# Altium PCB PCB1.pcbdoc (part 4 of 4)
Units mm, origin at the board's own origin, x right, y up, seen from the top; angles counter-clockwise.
Board outline 77.9 x 107.7 mm, 4 copper layers (Top Layer, Inner1, Inner2, Bottom Layer); 106 components, 123 nets, 650 pads, 272 vias.
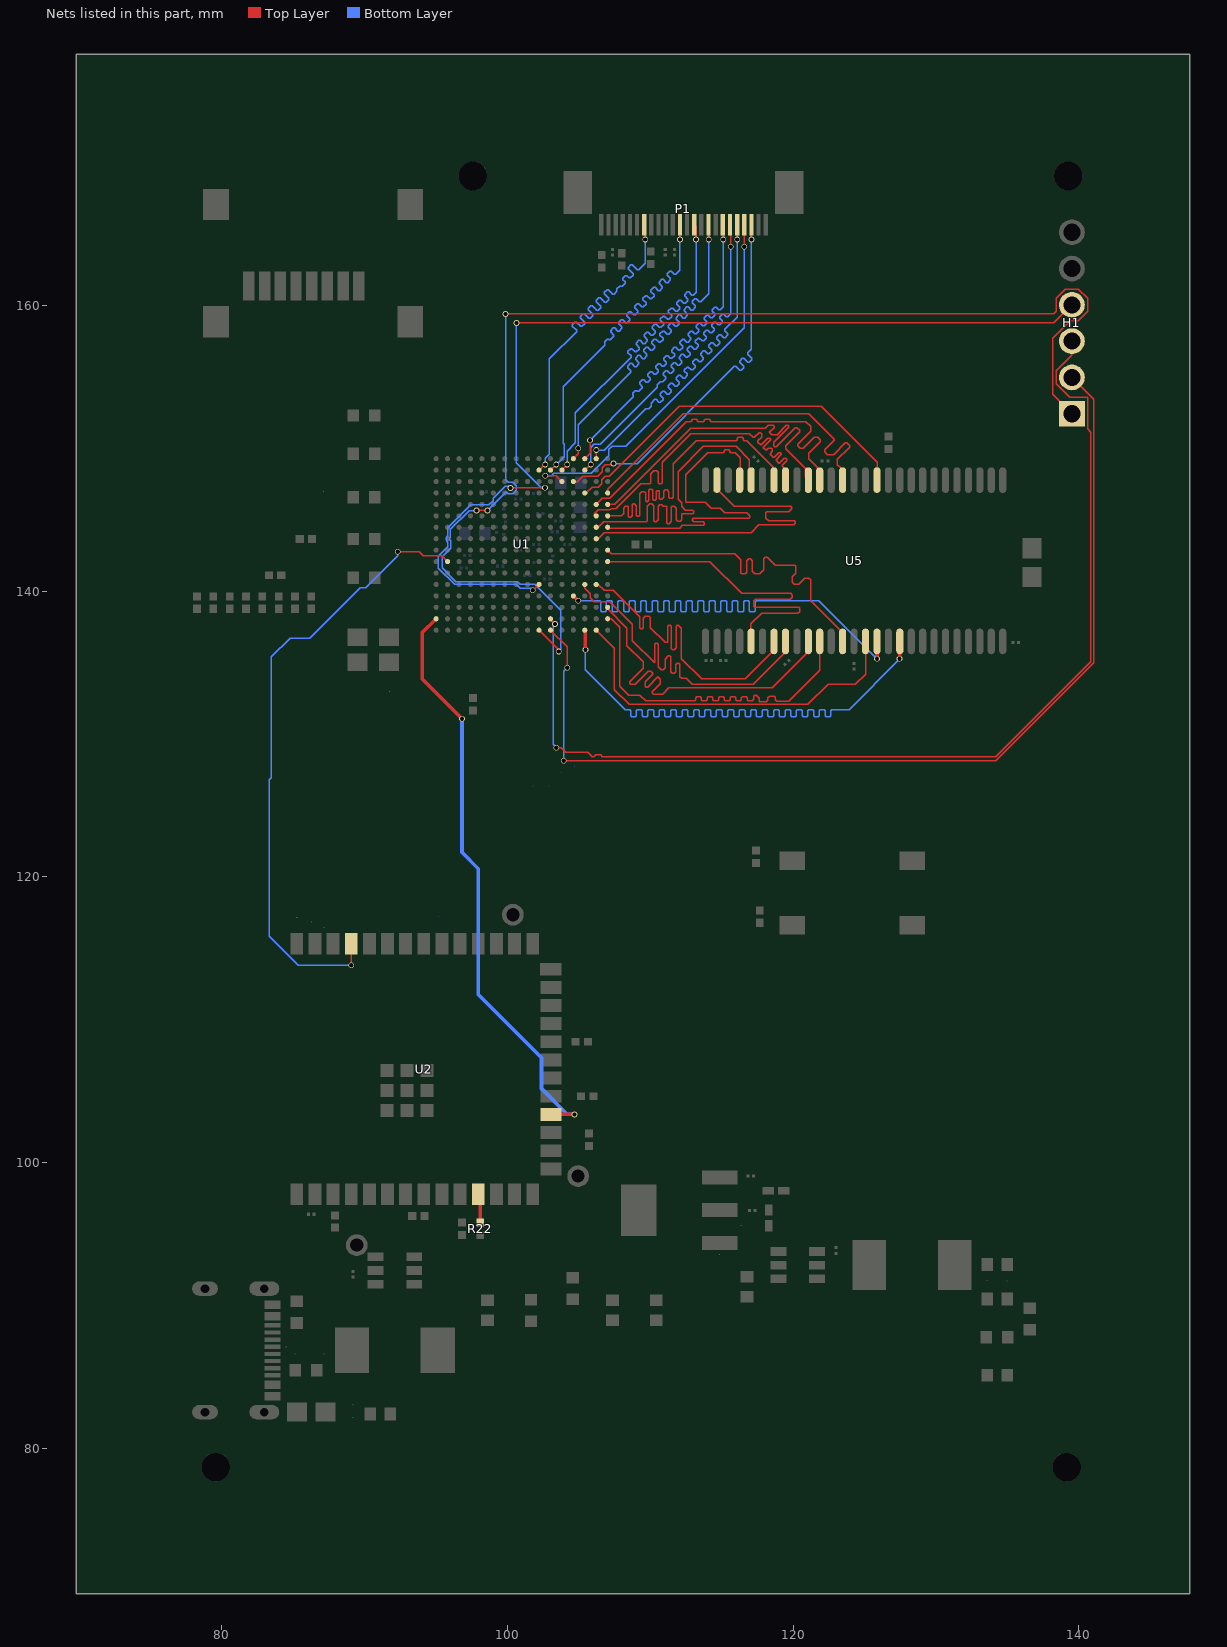
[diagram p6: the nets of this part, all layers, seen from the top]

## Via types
v1: diameter 0.4, hole 0.3, Top Layer to Bottom Layer, 269 vias
v2: diameter 0.5, hole 0.3, Top Layer to Bottom Layer, 3 vias

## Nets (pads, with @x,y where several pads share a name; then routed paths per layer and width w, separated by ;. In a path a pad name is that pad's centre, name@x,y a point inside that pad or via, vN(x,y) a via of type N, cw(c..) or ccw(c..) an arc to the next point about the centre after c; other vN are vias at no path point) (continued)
SD_DQ2: U1.K16 U5.5 | length 25.6
  Top Layer w0.1: U1.K16@107.024,142.06 114.162,142.06 116.391,139.831 119.82,139.831 119.947,139.704 119.947,139.577 119.803,139.434 117.372,139.434 117.262,139.323 117.262,138.919 117.322,138.859 120.384,138.859 120.455,138.788 120.455,138.561 120.329,138.435 117.789,138.435 117.048,137.694 117.048,136.873 117.065,136.856 U5.5@117.065,136.602
SD_DQ3: U1.M15 U5.7 | length 24.8
  Top Layer w0.1: U1.M15@106.224,140.46 106.303,140.46 106.318,140.445 106.366,140.445 106.769,140.042 107.417,140.042 109.263,138.195 109.263,137.418 109.334,137.347 109.434,137.347 109.505,137.418 109.505,138.095 109.66,138.25 109.914,138.25 110.014,138.15 110.014,137.445 111.057,136.402 111.184,136.402 111.242,136.46 111.242,137.545 111.312,137.616 111.412,137.616 111.483,137.545 111.483,135.976 111.565,135.894 111.692,135.894 111.815,136.018 111.815,137.545 111.874,137.604 111.958,137.604 112.18,137.382 112.18,135.279 113.597,133.862 116.65,133.862 118.521,135.733 118.521,136.331 118.538,136.348 118.538,136.475 U5.7@118.665,136.602
SD_DQ4: U1.M14 U5.8 | length 25.8
  Top Layer w0.1: U1.M14@105.424,140.46 105.424,140.2 105.806,139.818 105.806,139.538 106.102,139.242 107.182,139.242 108.744,137.68 108.744,136.529 110.302,134.971 110.334,135.003 110.334,136.275 110.404,136.346 110.504,136.346 110.575,136.275 110.575,134.698 110.776,134.497 110.93,134.497 111.049,134.616 111.049,135.238 111.267,135.457 111.367,135.457 111.438,135.386 111.438,134.343 111.538,134.243 111.692,134.243 111.784,134.335 111.784,134.831 111.902,134.949 112.002,134.949 112.073,134.878 112.073,134.011 112.2,133.884 112.54,133.884 112.943,133.481 117.214,133.481 119.622,135.889 119.622,136.445 U5.8@119.465,136.602
SD_DQ5: U1.P16 U5.10 | length 25.6
  Top Layer w0.1: U1.P16@107.024,138.86 107.024,138.751 108.369,137.406 108.369,136.169 109.503,135.035 109.503,134.581 108.573,133.652 108.573,133.552 108.644,133.481 108.964,133.481 109.853,134.37 110.041,134.37 110.168,134.243 110.168,134.177 109.647,133.657 109.647,133.341 109.718,133.271 109.818,133.271 110.543,133.995 110.711,133.826 110.711,133.504 110.161,132.953 110.161,132.853 110.231,132.782 110.866,132.782 111.311,133.227 118.542,133.227 121.065,135.75 U5.10@121.065,136.602
SD_DQ6: U1.R16 U5.11 | length 25.2
  Top Layer w0.1: U1.R16@107.024,138.06 107.288,138.06 107.882,137.466 107.882,133.354 108.513,132.723 109.275,132.723 109.676,132.322 113.117,132.322 113.188,132.393 113.188,132.521 113.259,132.592 113.517,132.592 113.588,132.521 113.588,132.393 113.659,132.322 113.917,132.322 113.988,132.393 113.988,132.521 114.059,132.592 114.317,132.592 114.388,132.521 114.388,132.393 114.459,132.322 114.717,132.322 114.788,132.393 114.788,132.521 114.859,132.592 115.117,132.592 115.188,132.521 115.188,132.393 115.259,132.322 115.517,132.322 115.588,132.393 115.588,132.521 115.659,132.592 115.917,132.592 115.988,132.521 115.988,132.393 116.059,132.322 116.317,132.322 116.388,132.393 116.388,132.521 116.459,132.592 116.717,132.592 116.788,132.521 116.788,132.393 116.859,132.322 117.136,132.322 117.236,132.422 117.236,132.648 117.307,132.719 117.407,132.719 117.613,132.513 117.613,132.262 118.125,132.262 118.225,132.362 118.225,132.521 118.352,132.648 118.677,132.648 118.748,132.578 118.748,132.392 118.848,132.292 119.679,132.292 121.852,134.465 U5.11@121.852,136.097
SD_DQ7: U1.J16 U5.13 | length 25.2
  Top Layer w0.1: U1.J16@107.024,142.86 107.259,142.625 115.91,142.625 116.347,142.188 116.347,141.286 116.418,141.215 116.659,141.215 116.759,141.315 116.759,142.117 116.896,142.253 117.016,142.253 117.155,142.115 117.155,141.38 117.319,141.215 117.648,141.215 117.931,141.498 117.931,142.26 118.042,142.371 118.185,142.371 118.753,141.803 118.757,141.807 120.13,141.807 120.201,141.736 120.201,141.237 119.947,140.983 119.947,140.609 120.09,140.466 120.387,140.466 120.822,140.902 121.09,140.902 121.219,140.772 121.219,139.338 ; 121.219,139.337 123.465,137.091 U5.13@123.465,136.602
SD_DQ8: U1.D16 U5.42 | length 25.2
  Top Layer w0.1: U1.D16@107.024,146.86 107.024,147.114 112.314,152.404 121.09,152.404 122.868,150.626 122.868,150.545 122.212,149.889 122.212,149.737 122.4,149.549 122.834,149.549 123.657,150.372 123.757,150.372 123.955,150.174 123.955,150.062 123.884,149.991 123.878,149.991 123.101,149.214 123.101,148.848 123.338,148.611 123.338,148.013 U5.42@123.465,147.886
SD_DQ9: U1.E15 U5.44 | length 25
  Top Layer w0.1: U1.E15@106.224,146.06 106.642,146.478 107.182,146.478 112.537,151.833 112.837,151.833 112.907,151.903 112.907,151.952 112.978,152.023 113.237,152.023 113.307,151.952 113.307,151.903 113.378,151.833 113.723,151.833 113.794,151.903 113.794,151.952 113.865,152.023 114.123,152.023 114.194,151.952 114.194,151.903 114.265,151.833 120.899,151.833 121.217,151.515 121.217,151.176 120.328,150.287 120.328,150.179 120.515,149.991 120.709,149.991 121.471,150.753 121.725,150.753 121.894,150.584 121.894,150.442 121.09,149.638 121.09,149.259 121.674,148.675 121.674,148.077 U5.44@121.865,147.886
SD_DQ10: U1.E16 U5.45 | length 25
  Top Layer w0.1: U1.E16@107.024,146.06 107.507,146.06 112.835,151.388 118.052,151.388 118.25,151.586 118.606,151.586 118.677,151.515 118.677,151.429 118.344,151.096 118.502,150.938 118.874,150.938 119.522,151.586 119.622,151.586 119.693,151.515 119.693,151.448 118.647,150.402 118.647,150.175 118.717,150.105 118.817,150.105 120.151,151.438 120.251,151.438 120.455,151.234 120.455,151.134 119.494,150.173 119.494,149.946 120.717,148.723 120.717,148.718 120.851,148.584 120.851,147.986 120.951,147.886 U5.45@121.065,147.886
SD_DQ11: U1.F15 U5.47 | length 25.1
  Top Layer w0.1: U1.F15@106.224,145.26 106.097,145.387 106.097,145.412 106.363,145.678 107.182,145.678 107.273,145.769 107.597,145.769 109.335,147.507 109.97,147.507 110.041,147.578 110.041,148.213 110.244,148.416 110.449,148.416 110.549,148.316 110.549,147.578 110.62,147.507 110.769,147.507 110.84,147.578 110.84,149.012 112.835,151.007 116.942,151.007 117.202,150.747 117.286,150.747 117.617,151.078 117.717,151.078 117.788,151.007 117.788,150.753 117.534,150.499 117.534,150.415 117.719,150.23 117.772,150.23 118.24,150.697 118.352,150.697 118.423,150.626 118.423,150.581 117.915,150.073 117.915,150.034 118.114,149.835 118.271,149.991 118.487,149.991 118.55,149.928 118.55,149.768 118.392,149.61 118.392,149.557 118.593,149.356 118.677,149.356 119.002,149.681 119.114,149.681 119.185,149.61 119.185,149.561 118.804,149.18 118.804,149.145 118.999,148.95 119.046,148.95 119.395,149.3 119.495,149.3 119.566,149.229 119.566,149.131 119.228,148.793 119.228,148.721 119.465,148.484 U5.47@119.465,147.886
SD_DQ12: U1.F16 U5.48 | length 25.1
  Top Layer w0.1: U1.F16@107.024,145.26 107.977,145.26 108.136,145.419 108.136,145.8 108.263,145.927 108.429,145.927 108.473,145.883 108.473,145.236 108.544,145.165 108.644,145.165 108.752,145.273 108.752,146.035 108.81,146.093 108.898,146.093 109.033,145.958 109.033,145.296 109.108,145.221 109.208,145.221 109.279,145.292 109.279,146.816 109.406,146.943 109.592,146.943 109.672,146.863 109.672,146.308 109.743,146.237 109.811,146.237 109.914,146.34 109.914,147.065 109.976,147.128 110.11,147.128 110.18,147.057 110.18,146.435 110.251,146.364 110.351,146.364 110.422,146.435 110.422,146.943 110.486,147.007 110.612,147.007 110.647,146.972 110.647,146.491 110.718,146.42 110.818,146.42 110.959,146.562 110.959,146.972 111.057,147.07 111.184,147.07 111.311,146.943 111.311,146.562 111.382,146.491 111.55,146.491 111.621,146.562 111.621,148.904 113.216,150.499 116.024,150.499 116.095,150.57 116.095,150.682 116.166,150.753 116.424,150.753 116.495,150.682 116.495,150.57 116.566,150.499 116.772,150.499 118.606,148.664 118.606,147.986 118.665,147.928 U5.48@118.665,147.886
SD_DQ13: U1.G15 U5.50 | length 25.1
  Top Layer w0.1: U1.G15@106.224,144.46 106.365,144.46 106.747,144.842 109.718,144.842 109.787,144.911 109.787,145.927 109.97,146.11 110.112,146.11 110.239,145.983 110.239,144.911 110.309,144.84 110.409,144.84 110.549,144.98 110.549,145.927 110.676,146.054 110.803,146.054 110.93,145.927 111.146,145.927 111.146,144.784 111.217,144.713 111.317,144.713 111.476,144.873 111.476,145.87 111.533,145.927 111.692,145.927 111.819,145.8 111.819,144.984 111.919,144.884 112.1,144.884 112.2,144.984 112.2,145.377 112.241,145.419 112.962,145.419 113.033,145.49 113.033,145.59 112.954,145.668 112.459,145.668 112.2,145.927 112.2,146.168 111.957,146.411 111.957,148.358 113.718,150.118 116.01,150.118 116.946,149.181 116.946,148.005 U5.50@117.065,147.886
SD_DQ14: U1.G16 U5.51 | length 25
  Top Layer w0.1: U1.G16@107.024,144.46 107.087,144.396 112.066,144.396 112.26,144.59 113.724,144.59 113.795,144.661 113.795,144.761 113.724,144.831 113.041,144.831 112.929,144.944 112.929,145.005 113.023,145.1 116.899,145.1 116.97,145.17 116.97,145.27 116.75,145.49 115.204,145.49 114.894,145.8 114.27,145.8 113.851,146.219 112.501,146.219 112.501,148.133 114.041,149.674 115.105,149.674 115.176,149.744 115.176,149.818 115.246,149.889 115.505,149.889 115.576,149.818 115.576,149.744 115.646,149.674 115.946,149.674 116.311,149.309 116.311,148.221 U5.51@116.328,148.204
SD_DQ15: U1.H15 U5.53 | length 25.3
  Top Layer w0.1: U1.H15@106.224,143.66 106.351,143.66 106.769,144.078 117.055,144.078 117.612,144.635 120.039,144.635 120.145,144.74 120.145,144.84 120.074,144.911 118.296,144.911 118.098,145.109 118.098,145.475 118.169,145.546 119.68,145.546 119.891,145.756 119.891,145.856 119.82,145.927 115.883,145.927 114.792,147.018 U5.53@114.792,147.759
SD_DQM0: U1.T15 U5.15 | length 25.8
  Top Layer w0.1: U1.T15@106.224,137.26 107.501,135.983 107.501,133.1 108.539,132.062 121.034,132.062 122.453,133.481 124.352,133.481 125.065,134.194 U5.15@125.065,136.475
SD_DQM1: U1.D14 U5.39 | length 25.9
  Top Layer w0.1: U1.D14@105.424,146.86 105.513,146.86 105.931,147.278 106.382,147.278 106.606,147.502 106.606,147.782 106.866,148.042 107.146,148.042 112.016,152.912 121.963,152.912 125.874,149.002 125.874,148.013 U5.39@125.747,147.886
SD_RAS_N: U1.T14 U5.18 | length 43.8
  Top Layer w0.254: v1(105.469,135.894) U1.T14@105.469,137.094 ; v1(127.44,135.259) 127.465,135.284 U5.18@127.465,136.475
  Bottom Layer w0.1: v1(105.469,135.894) 105.469,134.497 108.263,131.703 108.563,131.703 108.634,131.632 108.634,131.266 108.704,131.195 108.963,131.195 109.034,131.266 109.034,131.632 109.104,131.703 109.363,131.703 109.434,131.632 109.434,131.266 109.504,131.195 109.763,131.195 109.834,131.266 109.834,131.632 109.904,131.703 110.163,131.703 110.234,131.632 110.234,131.266 110.304,131.195 110.563,131.195 110.634,131.266 110.634,131.632 110.704,131.703 110.963,131.703 111.034,131.632 111.034,131.266 111.104,131.195 111.363,131.195 111.434,131.266 111.434,131.632 111.504,131.703 111.763,131.703 111.834,131.632 111.834,131.266 111.904,131.195 112.163,131.195 112.234,131.266 112.234,131.632 112.304,131.703 112.563,131.703 112.634,131.632 112.634,131.266 112.704,131.195 112.963,131.195 113.034,131.266 113.034,131.632 113.104,131.703 113.363,131.703 113.434,131.632 113.434,131.266 113.504,131.195 113.763,131.195 113.834,131.266 113.834,131.632 113.904,131.703 114.163,131.703 114.234,131.632 114.234,131.266 114.304,131.195 114.563,131.195 114.634,131.266 114.634,131.632 114.704,131.703 114.963,131.703 115.034,131.632 115.034,131.266 115.104,131.195 115.363,131.195 115.434,131.266 115.434,131.632 115.504,131.703 115.763,131.703 115.834,131.632 115.834,131.266 115.904,131.195 116.163,131.195 116.234,131.266 116.234,131.632 116.304,131.703 116.563,131.703 116.634,131.632 116.634,131.266 116.704,131.195 116.963,131.195 117.034,131.266 117.034,131.632 117.104,131.703 117.363,131.703 117.434,131.632 117.434,131.266 117.504,131.195 117.763,131.195 117.834,131.266 117.834,131.632 117.904,131.703 118.163,131.703 118.234,131.632 118.234,131.266 118.304,131.195 118.563,131.195 118.634,131.266 118.634,131.632 118.704,131.703 118.963,131.703 119.034,131.632 119.034,131.266 119.104,131.195 119.363,131.195 119.434,131.266 119.434,131.632 119.504,131.703 119.763,131.703 119.834,131.632 119.834,131.266 119.904,131.195 120.163,131.195 120.234,131.266 120.234,131.632 120.304,131.703 120.563,131.703 120.634,131.632 120.634,131.266 120.704,131.195 120.963,131.195 121.034,131.266 121.034,131.632 121.104,131.703 121.363,131.703 121.434,131.632 121.434,131.266 121.504,131.195 121.763,131.195 121.834,131.266 121.834,131.632 121.904,131.703 122.163,131.703 122.234,131.632 122.234,131.266 122.304,131.195 122.563,131.195 122.634,131.266 122.634,131.632 122.704,131.703 123.931,131.703 127.44,135.211 v1(127.44,135.259)
SD_WE_N: U1.N13 U5.16 | length 43.3
  Top Layer w0.254: U1.N13@104.624,139.66 v1(104.961,139.323) ; v1(125.865,135.259) U5.16@125.865,136.475
  Bottom Layer w0.1: v1(104.961,139.323) 106.469,139.323 106.54,139.252 106.54,138.632 106.61,138.561 106.869,138.561 106.94,138.632 106.94,139.252 107.01,139.323 107.269,139.323 107.34,139.252 107.34,138.632 107.41,138.561 107.669,138.561 107.74,138.632 107.74,139.252 107.81,139.323 108.069,139.323 108.14,139.252 108.14,138.632 108.21,138.561 108.469,138.561 108.54,138.632 108.54,139.252 108.61,139.323 108.869,139.323 108.94,139.252 108.94,138.632 109.01,138.561 109.269,138.561 109.34,138.632 109.34,139.252 109.41,139.323 109.669,139.323 109.74,139.252 109.74,138.632 109.81,138.561 110.069,138.561 110.14,138.632 110.14,139.252 110.21,139.323 110.469,139.323 110.54,139.252 110.54,138.632 110.61,138.561 110.869,138.561 110.94,138.632 110.94,139.252 111.01,139.323 111.269,139.323 111.34,139.252 111.34,138.632 111.41,138.561 111.669,138.561 111.74,138.632 111.74,139.252 111.81,139.323 112.069,139.323 112.14,139.252 112.14,138.632 112.21,138.561 112.469,138.561 112.54,138.632 112.54,139.252 112.61,139.323 112.869,139.323 112.94,139.252 112.94,138.632 113.01,138.561 113.269,138.561 113.34,138.632 113.34,139.252 113.41,139.323 113.669,139.323 113.74,139.252 113.74,138.632 113.81,138.561 114.069,138.561 114.14,138.632 114.14,139.252 114.21,139.323 114.469,139.323 114.54,139.252 114.54,138.632 114.61,138.561 114.869,138.561 114.94,138.632 114.94,139.252 115.01,139.323 115.269,139.323 115.34,139.252 115.34,138.632 115.41,138.561 115.669,138.561 115.74,138.632 115.74,139.252 115.81,139.323 116.069,139.323 116.14,139.252 116.14,138.632 116.21,138.561 116.469,138.561 116.54,138.632 116.54,139.252 116.61,139.323 116.869,139.323 116.94,139.252 116.94,138.632 117.01,138.561 117.269,138.561 117.34,138.632 117.34,139.252 117.41,139.323 121.801,139.323 v1(125.865,135.259)
SDA: R22.1 U2.11 | length 1.9
  Top Layer w0.254: R22.1@98.098,95.889 U2.11@98.098,97.807
SSPI_CS_N: U1.R1 U2.18 | length 41.3
  Top Layer w0.254: U1.R1@95.024,138.06 94.039,137.075 94.039,133.862 v1(96.833,131.068) ; U2.18@103.188,103.382 v1(104.707,103.382)
  Bottom Layer w0.254: v1(96.833,131.068) 96.833,121.714 97.976,120.571 97.976,111.764 102.394,107.346 102.394,105.187 104.199,103.382 v1(104.707,103.382)
TCK: H1.1 U1.T10 | length 88.4
  Top Layer w0.1: v1(97.845,145.632) 98.056,145.632 98.065,145.642 98.382,145.642 98.392,145.632 98.57,145.632 v1@98.611,145.673 ; v1(99.881,159.389) 138.219,159.389 138.403,159.573 138.403,160.48 139.048,161.126 139.961,161.126 140.607,160.48 140.607,159.568 139.961,158.922 139.384,158.922 138.152,157.69 138.152,153.757 H1.1@139.505,152.404 ; U1.T10@102.224,137.26 103.608,135.876 v1(103.608,135.767)
  Bottom Layer w0.1: v1(97.845,145.632) 97.329,145.632 96.026,144.329 96.026,143.773 95.976,143.723 95.976,143.571 96.038,143.509 96.038,143.011 95.436,142.409 95.436,141.638 96.408,140.666 100.706,140.666 100.895,140.477 101.927,140.477 103.739,138.666 103.739,135.898 v1(103.608,135.767) ; v1(98.611,145.632) 99.881,146.902 99.965,146.902 100.057,146.81 100.39,146.81 100.626,147.046 100.626,147.379 100.39,147.614 100.057,147.614 99.881,147.791 v1(99.881,159.389)
TDI: H1.3 U1.R11 | length 74.5
  Top Layer w0.1: U1.R11@103.024,138.06 103.024,138.012 v1(103.337,137.699) ; v1(103.437,129.036) 103.765,129.036 104.092,128.709 105.642,128.709 105.95,128.401 106.064,128.401 106.191,128.528 106.524,128.528 106.651,128.401 134.171,128.401 140.829,135.059 140.829,151.124 140.616,151.337 140.616,153.55 139.34,153.55 138.403,154.488 138.403,155.4 139.505,156.502 H1.3@139.505,157.484
  Bottom Layer w0.1: v1(103.337,137.699) 103.206,137.568 103.206,129.267 v1(103.437,129.036)
TDO: H1.4 U1.M10 | length 71.1
  Top Layer w0.1: v1(100.224,147.212) 100.253,147.242 102.63,147.242 v1(102.642,147.23) ; v1(100.643,158.754) 138.235,158.754 H1.4@139.505,160.024 ; v1(101.786,140.05) 101.814,140.05 U1.M10@102.224,140.46
  Bottom Layer w0.1: v1(100.224,147.212) 100.097,147.339 99.867,147.339 99.013,146.485 99.013,146.328 98.719,146.034 97.448,146.034 95.826,144.412 95.826,143.855 95.776,143.806 95.776,143.488 95.838,143.427 95.838,143.093 95.182,142.437 95.182,141.609 96.325,140.466 100.624,140.466 100.912,140.177 101.659,140.177 v1(101.786,140.05) ; v1(100.643,158.754) 100.643,148.962 102.375,147.23 v1(102.642,147.23)
TMS: H1.2 U1.T11 | length 70.2
  Top Layer w0.1: U1.T11@103.024,137.26 104.199,136.085 v1(104.199,134.624) ; v1(103.945,128.126) 134.179,128.126 141.029,134.976 141.029,153.42 H1.2@139.505,154.944
  Bottom Layer w0.1: v1(103.945,128.126) 103.945,134.37 v1(104.199,134.624)
TX: U1.K2 U2.37 | length 43.6
  Top Layer w0.1: v1@89.081,113.796 U2.37@89.081,115.307 ; v1@92.261,142.752 93.851,142.752 94.126,142.477 95.405,142.477 ; 95.406,142.478 U1.K2@95.824,142.06
  Bottom Layer w0.1: v1(89.081,113.817) 85.382,113.817 83.348,115.851 83.348,126.78 83.498,126.93 83.498,135.386 84.822,136.71 86.194,136.71 89.729,140.245 90.097,140.245 92.336,142.484 v1(92.336,142.752)
VSYNC: P1.7 U1.B10 | length 27.1
  Top Layer w0.1: U1.B10@102.224,148.46 102.619,148.856 v1(102.667,148.856) ; P1.7@109.581,165.626 109.66,165.548 v1(109.66,164.596)
  Bottom Layer w0.1: v1(102.667,148.856) 102.667,149.288 102.95,149.57 102.95,156.235 104.845,158.13 104.845,158.23 104.536,158.539 104.536,158.639 104.719,158.822 104.819,158.822 105.128,158.513 105.228,158.513 105.411,158.696 105.411,158.796 105.101,159.105 105.101,159.205 105.284,159.388 105.384,159.388 105.693,159.079 105.793,159.079 105.976,159.261 105.976,159.361 105.667,159.671 105.667,159.771 105.85,159.953 105.95,159.953 106.259,159.644 106.359,159.644 106.542,159.827 106.542,159.927 106.233,160.236 106.233,160.336 106.416,160.519 106.516,160.519 106.825,160.21 106.925,160.21 107.108,160.393 107.108,160.493 106.798,160.802 106.798,160.902 106.981,161.085 107.081,161.085 107.39,160.776 107.49,160.776 107.677,160.962 107.677,161.155 107.864,161.341 108.056,161.341 108.239,161.524 108.239,161.624 108.073,161.79 108.073,161.89 108.256,162.073 108.356,162.073 108.522,161.907 108.622,161.907 108.805,162.09 108.805,162.19 108.46,162.534 108.46,162.634 108.643,162.817 108.743,162.817 109.088,162.473 109.188,162.473 109.66,162.945 v1(109.66,164.596)
Y2: P1.19 U1.B14 | length 27
  Top Layer w0.1: U1.B14@105.424,148.46 105.812,148.848 v1(105.85,148.848) ; P1.19@115.58,165.626 115.629,165.578 v1(115.629,164.088)
  Bottom Layer w0.1: v1(105.85,148.848) 105.85,149.676 105.829,149.697 105.829,150.031 106.064,150.266 106.506,150.266 110.51,154.27 110.51,154.436 110.71,154.636 110.876,154.636 111.091,154.852 111.091,154.952 110.903,155.14 110.903,155.24 111.086,155.422 111.186,155.422 111.374,155.234 111.474,155.234 111.657,155.417 111.657,155.517 111.469,155.705 111.469,155.805 111.652,155.988 111.752,155.988 111.94,155.8 112.04,155.8 112.223,155.983 112.223,156.083 112.035,156.271 112.035,156.371 112.218,156.554 112.318,156.554 112.506,156.366 112.606,156.366 112.788,156.549 112.788,156.649 112.6,156.837 112.6,156.937 112.783,157.12 112.883,157.12 113.071,156.932 113.171,156.932 113.354,157.114 113.354,157.214 113.166,157.402 113.166,157.502 113.349,157.685 113.449,157.685 113.637,157.497 113.737,157.497 113.92,157.68 113.92,157.78 113.732,157.968 113.732,158.068 113.915,158.251 114.015,158.251 114.203,158.063 114.303,158.063 114.486,158.246 114.486,158.346 114.298,158.534 114.298,158.634 114.48,158.817 114.58,158.817 114.768,158.629 114.868,158.629 115.051,158.811 115.051,158.911 114.863,159.099 114.863,159.199 115.046,159.382 115.146,159.382 115.334,159.194 115.434,159.194 115.629,159.389 v1(115.629,164.088)
Y3: P1.21 U1.C12 | length 27
  Top Layer w0.1: v1(102.661,148.071) 103.413,148.071 U1.C12@103.824,147.66 ; v1(116.583,164.088) P1.21@116.583,165.623
  Bottom Layer w0.1: v1(102.661,148.071) 103.11,148.071 103.269,148.23 105.867,148.23 107.099,149.462 107.099,149.904 107.334,150.139 108.284,150.139 116.583,158.438 v1(116.583,164.088)
Y4: P1.22 U1.C13 | length 27
  Top Layer w0.1: U1.C13@104.624,147.66 104.884,147.66 105.266,148.042 106.346,148.042 106.642,148.338 106.642,148.618 106.866,148.842 107.358,148.842 v1(107.432,148.916) ; v1(117.083,164.596) P1.22@117.083,165.623
  Bottom Layer w0.1: v1(107.432,148.916) 109.093,148.916 115.888,155.711 115.988,155.711 116.269,155.43 116.369,155.43 116.552,155.613 116.552,155.713 116.271,155.994 116.271,156.094 116.454,156.277 116.554,156.277 116.835,155.996 116.935,155.996 117.117,156.179 117.117,156.279 116.836,156.56 116.836,156.66 117.083,156.906 v1(117.083,164.596)
Y5: P1.20 U1.A15 | length 27
  Top Layer w0.1: U1.A15@106.224,149.26 106.231,149.267 v1(106.231,149.864) ; v1(116.083,164.596) P1.20@116.083,165.623
  Bottom Layer w0.1: v1(106.231,149.864) 106.776,149.864 109.674,152.762 109.774,152.762 109.782,152.753 109.882,152.753 110.065,152.936 110.065,153.036 110.057,153.045 110.057,153.145 110.317,153.405 110.417,153.405 110.616,153.206 110.716,153.206 110.899,153.389 110.899,153.489 110.7,153.688 110.7,153.788 110.883,153.97 110.983,153.97 111.181,153.772 111.281,153.772 111.464,153.955 111.464,154.055 111.266,154.253 111.266,154.353 111.448,154.536 111.548,154.536 111.747,154.337 111.847,154.337 112.03,154.52 112.03,154.62 111.831,154.819 111.831,154.919 112.014,155.102 112.114,155.102 112.313,154.903 112.413,154.903 112.596,155.086 112.596,155.186 112.397,155.385 112.397,155.485 112.58,155.667 112.68,155.667 112.879,155.469 112.979,155.469 113.161,155.652 113.161,155.752 112.963,155.95 112.963,156.05 113.146,156.233 113.246,156.233 113.444,156.034 113.544,156.034 113.727,156.217 113.727,156.317 113.528,156.516 113.528,156.616 113.711,156.799 113.811,156.799 114.01,156.6 114.11,156.6 114.293,156.783 114.293,156.883 114.094,157.082 114.094,157.182 114.277,157.364 114.377,157.364 114.576,157.166 114.676,157.166 114.858,157.349 114.858,157.449 114.66,157.647 114.66,157.747 114.843,157.93 114.943,157.93 115.141,157.731 115.241,157.731 115.424,157.914 115.424,158.014 115.225,158.213 115.225,158.313 116.083,159.17 v1(116.083,164.596)
Y6: P1.18 U1.A14 | length 27.1
  Top Layer w0.1: U1.A14@105.424,149.26 105.789,149.625 v1(105.789,150.56) ; P1.18@115.081,165.626 115.121,165.586 v1(115.121,164.596)
  Bottom Layer w0.1: v1(105.789,150.56) 108.828,153.598 108.828,153.698 108.782,153.743 108.782,153.843 108.965,154.026 109.065,154.026 109.11,153.981 109.21,153.981 109.439,154.21 109.439,154.31 109.254,154.495 109.254,154.595 109.437,154.778 109.537,154.778 109.722,154.592 109.822,154.592 110.005,154.775 110.005,154.875 109.82,155.061 109.82,155.161 110.003,155.343 110.103,155.343 110.288,155.158 110.388,155.158 110.571,155.341 110.571,155.441 110.385,155.626 110.385,155.726 110.568,155.909 110.668,155.909 110.854,155.724 110.954,155.724 111.136,155.907 111.136,156.007 110.951,156.192 110.951,156.292 111.134,156.475 111.234,156.475 111.419,156.289 111.519,156.289 111.702,156.472 111.702,156.572 111.517,156.758 111.517,156.858 111.7,157.041 111.8,157.041 111.985,156.855 112.085,156.855 112.268,157.038 112.268,157.138 112.082,157.323 112.082,157.423 112.265,157.606 112.365,157.606 112.551,157.421 112.651,157.421 112.833,157.604 112.833,157.704 112.648,157.889 112.648,157.989 112.831,158.172 112.931,158.172 113.116,157.987 113.216,157.987 113.399,158.169 113.399,158.269 113.214,158.455 113.214,158.555 113.397,158.738 113.497,158.738 113.682,158.552 113.782,158.552 113.965,158.735 113.965,158.835 113.779,159.02 113.779,159.12 113.962,159.303 114.062,159.303 114.248,159.118 114.348,159.118 114.531,159.301 114.531,159.401 114.345,159.586 114.345,159.686 114.528,159.869 114.628,159.869 114.813,159.684 114.913,159.684 115.121,159.891 v1(115.121,164.596)
Y7: P1.16 U1.A13 | length 26.9
  Top Layer w0.1: U1.A13@104.624,149.26 104.961,149.597 v1(104.961,149.991) ; P1.16@114.081,165.625 114.105,165.601 v1(114.105,164.596)
  Bottom Layer w0.1: v1(104.961,149.991) 104.961,151.642 108.639,155.32 108.639,155.42 108.421,155.638 108.421,155.738 108.604,155.92 108.704,155.92 108.922,155.703 109.022,155.703 109.205,155.886 109.205,155.986 108.987,156.203 108.987,156.303 109.17,156.486 109.27,156.486 109.487,156.269 109.587,156.269 109.77,156.451 109.77,156.551 109.553,156.769 109.553,156.869 109.736,157.052 109.836,157.052 110.053,156.834 110.153,156.834 110.336,157.017 110.336,157.117 110.118,157.335 110.118,157.435 110.301,157.617 110.401,157.617 110.619,157.4 110.719,157.4 110.902,157.583 110.902,157.683 110.684,157.9 110.684,158 110.867,158.183 110.967,158.183 111.184,157.966 111.284,157.966 111.467,158.148 111.467,158.248 111.25,158.466 111.25,158.566 111.433,158.749 111.533,158.749 111.75,158.531 111.85,158.531 112.033,158.714 112.033,158.814 111.815,159.032 111.815,159.132 111.998,159.314 112.098,159.314 112.316,159.097 112.416,159.097 112.599,159.28 112.599,159.38 112.381,159.597 112.381,159.697 112.564,159.88 112.664,159.88 112.881,159.663 112.981,159.663 113.164,159.845 113.164,159.945 112.947,160.163 112.947,160.263 113.13,160.446 113.23,160.446 113.447,160.228 113.547,160.228 114.105,160.786 v1(114.105,164.596)
Y8: P1.14 U1.B12 | length 27
  Top Layer w0.1: U1.B12@103.824,148.46 104.199,148.835 v1(104.199,148.848) ; P1.14@113.081,165.626 113.212,165.495 v1(113.212,164.592)
  Bottom Layer w0.1: v1(104.199,148.848) 104.199,149.798 104.761,150.36 104.761,152.458 108.659,156.356 108.659,156.456 108.441,156.673 108.441,156.773 108.624,156.956 108.724,156.956 108.942,156.739 109.042,156.739 109.235,156.932 109.235,157.032 109.018,157.25 109.018,157.35 109.2,157.533 109.3,157.533 109.518,157.315 109.618,157.315 109.801,157.498 109.801,157.598 109.583,157.815 109.583,157.915 109.766,158.098 109.866,158.098 110.084,157.881 110.184,157.881 110.366,158.064 110.366,158.164 110.149,158.381 110.149,158.481 110.332,158.664 110.432,158.664 110.649,158.446 110.749,158.446 110.932,158.629 110.932,158.729 110.715,158.947 110.715,159.047 110.897,159.23 110.997,159.23 111.215,159.012 111.315,159.012 111.498,159.195 111.498,159.295 111.28,159.512 111.28,159.612 111.463,159.795 111.563,159.795 111.781,159.578 111.881,159.578 112.063,159.761 112.063,159.861 111.846,160.078 111.846,160.178 112.029,160.361 112.129,160.361 112.346,160.144 112.446,160.144 112.629,160.326 112.629,160.426 112.412,160.644 112.412,160.744 112.595,160.927 112.695,160.927 112.912,160.709 113.012,160.709 113.212,160.909 v1(113.212,164.592)
Y9: P1.12 U1.B11 | length 27
  Top Layer w0.1: U1.B11@103.024,148.46 103.412,148.848 v1(103.437,148.848) ; v1(112.081,164.596) P1.12@112.081,165.626
  Bottom Layer w0.1: v1(103.437,148.848) 103.999,149.41 103.999,150.257 103.924,150.332 103.924,154.288 106.836,157.2 106.836,157.3 106.809,157.327 106.809,157.427 106.992,157.61 107.092,157.61 107.119,157.583 107.219,157.583 107.445,157.809 107.445,157.909 107.228,158.127 107.228,158.227 107.41,158.41 107.51,158.41 107.728,158.192 107.828,158.192 108.011,158.375 108.011,158.475 107.793,158.692 107.793,158.792 107.976,158.975 108.076,158.975 108.294,158.758 108.394,158.758 108.576,158.941 108.576,159.041 108.359,159.258 108.359,159.358 108.542,159.541 108.642,159.541 108.859,159.324 108.959,159.324 109.142,159.506 109.142,159.606 108.925,159.824 108.925,159.924 109.108,160.107 109.208,160.107 109.425,159.889 109.525,159.889 109.708,160.072 109.708,160.172 109.49,160.39 109.49,160.49 109.673,160.672 109.773,160.672 109.991,160.455 110.091,160.455 110.274,160.638 110.274,160.738 110.056,160.955 110.056,161.055 110.239,161.238 110.339,161.238 110.556,161.021 110.656,161.021 110.839,161.203 110.839,161.303 110.622,161.521 110.622,161.621 110.805,161.804 110.905,161.804 111.122,161.586 111.222,161.586 111.405,161.769 111.405,161.869 111.187,162.087 111.187,162.187 111.37,162.369 111.47,162.369 111.688,162.152 111.788,162.152 112.081,162.446 v1(112.081,164.596)
pads on no net: P1.1 P1.23 P1.24 SCREW1.1 SCREW2.1 SCREW3.1 SCREW4.1 U1.A9 U1.B3 U1.B8 U1.B15 U1.B16 U1.C1 U1.C2 U1.C3 U1.C4 U1.C5 U1.C6 U1.C8 U1.C9 U1.C10 U1.C11 U1.C14 U1.C15 U1.C16 U1.D1 U1.D3 U1.D4 U1.D5 U1.D6 U1.D7 U1.D8 U1.D9 U1.D10 U1.D11 U1.D12 U1.D13 U1.E3 U1.E4 U1.E5 U1.E6 U1.E7 U1.E8 U1.E9 U1.E10 U1.E11 U1.E12 U1.E13 U1.E14 U1.F3 U1.F4 U1.F5 U1.F12 U1.F13 U1.F14 U1.G3 U1.G4 U1.G5 U1.G12 U1.G13 U1.G14 U1.H2 U1.H3 U1.H4 U1.H5 U1.H12 U1.H13 U1.H14 U1.J3 U1.J4 U1.J5 U1.J12 U1.J13 U1.K3 U1.K4 U1.K5 U1.K13 U1.K14 U1.K15 U1.L1 U1.L2 U1.L3 U1.L4 U1.L5 U1.L13 U1.L14 U1.L16 U1.M2 U1.M3 U1.M4 U1.M5 U1.M6 U1.M7 U1.M9 U1.M11 U1.M12 U1.M13 U1.N1 U1.N3 U1.N4 U1.N5 U1.N6 U1.N7 U1.N8 U1.N9 U1.N11 U1.N12 U1.N14 U1.N16 U1.P1 U1.P2 U1.P3 U1.P4 U1.P5 U1.P6 U1.P7 U1.P8 U1.P11 U1.P12 U1.P13 U1.P14 U1.P15 U1.R2 U1.R3 U1.R4 U1.R5 U1.R6 U1.R7 U1.R8 U1.R12 U1.R14 U1.T13 U2.4 U2.15 U2.16 U2.26 U2.28 U2.29 U2.30 U2.32 U2.33 U2.34 U2.35 U2.38 U2.39 U5.40 U8.4 USB1.A8 USB1.B6 USB1.B7 USB1.B8
copper on no net: | length 22.1
  Top Layer w0.1: 86.292,116.844 86.541,116.595 86.541,115.307 ; 87.181,116.463 87.811,115.833 87.811,115.307 ; 89.081,97.807 89.31,97.578 v1(89.31,96.173) ; 97.971,115.307 97.971,115.942 99.508,117.479 100.135,117.479 100.389,117.225 ; v1@102.675,138.561 102.725,138.561 103.024,138.86 ; 103.061,99.572 104.072,99.572 104.58,99.064
  Top Layer w0.254: v1(94.166,138.892) 94.992,138.892 95.024,138.86 ; v1(94.337,141.4) 94.477,141.26 95.024,141.26 ; v1(94.42,139.704) 94.98,139.704 95.024,139.66 ; v1(95.421,139.305) 95.824,138.901 95.824,138.86 ; v1(96.219,139.217) 96.219,139.255 96.624,139.66 ; v1(96.976,138.46) 97.024,138.46 97.424,138.86 ; v1(97.087,139.323) 97.424,139.66 ; v1@97.826,138.411 97.826,138.462 98.224,138.86 ; v1(97.849,139.323) 97.887,139.323 98.224,139.66 ; v1@98.611,139.323 98.687,139.323 99.024,139.66 ; v1(98.692,138.48) 99.024,138.812 99.024,138.86 ; v1@99.373,139.196 99.373,139.209 99.824,139.66
  Bottom Layer w0.1: v1(89.31,96.173) 89.467,96.016 89.467,94.238 ; v1(93.15,141.272) 94.21,141.272 v1(94.337,141.4) ; v1(102.676,138.56) 103.056,138.18 103.056,138.053
  other v1: 97.824,138.413 99.406,139.23 98.625,139.309

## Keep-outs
Board Outline Layer:
  lines w0.254: 77.402,76.2 141.402,76.2 141.402,171.2 77.402,171.2 77.402,76.2

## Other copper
Top Layer:
  region net GND: 85.019,117.367 85.527,117.367 85.527,116.966 85.014,116.966 85.019,116.971
  region net DN: 84.897,86.819 85.405,86.819 85.405,86.417 84.892,86.417 84.897,86.423
  region net DP: 84.262,87.327 84.77,87.327 84.77,86.925 84.257,86.925 84.262,86.931
  region net GND: 86.929,86.819 87.437,86.819 87.437,86.417 86.924,86.417 86.929,86.423
  region net GND: 88.961,82.374 89.469,82.374 89.469,81.972 88.956,81.972 88.961,81.978
  region net +5V: 88.942,83.282 89.45,83.282 89.45,82.88 88.937,82.88 88.942,82.886
  region net +1V8: 116.09,95.799 116.598,95.799 116.598,95.397 116.085,95.397 116.09,95.402
  region net GND: 114.609,93.768 115.117,93.768 115.117,93.367 114.604,93.367 114.609,93.372
  region net GND: 134.726,91.928 135.234,91.928 135.234,91.527 134.72,91.527 134.726,91.532
  region net +3V3: 86.899,147.165 87.407,147.165 87.407,146.764 86.894,146.764 86.899,146.769
  region net GND: 91.501,133.174 92.009,133.174 92.009,132.772 91.496,132.772 91.501,132.778
  region net +1V1: 133.326,91.967 133.834,91.967 133.834,91.566 133.32,91.566 133.326,91.571
  region: 86.04,117.045 86.548,117.045 86.548,116.643 86.035,116.643 86.04,116.649
  region: 86.929,116.664 87.437,116.664 87.437,116.262 86.924,116.262 86.929,116.268
Bottom Layer:
  region net DONE: 103.51,127.515 104.018,127.515 104.018,127.114 103.504,127.114 103.51,127.119
  region net +1V1: 104.455,127.942 104.963,127.942 104.963,127.541 104.45,127.541 104.455,127.546
  region net PROGRAMN: 101.534,126.548 102.042,126.548 102.042,126.147 101.529,126.147 101.534,126.152
  region net INITN: 94.93,117.426 95.438,117.426 95.438,117.024 94.925,117.024 94.93,117.03
  region net GND: 102.677,126.57 103.185,126.57 103.185,126.168 102.672,126.168 102.677,126.174
  region: 102.738,138.228 103.178,138.482 103.378,138.135 102.934,137.878 102.936,137.885

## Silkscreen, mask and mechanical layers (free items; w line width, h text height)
Top Silkscreen Layer:
  text "JTAG" at 137.621,156.297 h3.05 r90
